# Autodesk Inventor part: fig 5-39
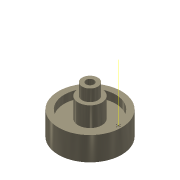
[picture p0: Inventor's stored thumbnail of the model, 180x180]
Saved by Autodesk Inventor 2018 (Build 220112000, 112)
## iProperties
Shininess: 65.0
Length Units: 11269
Angle Units: 11279
Time Units: 11290
Mass Units: 11283
Length Display Precision: 3
Angle Display Precision: 2
Created: 2001-11
Part Number: fig 5-39
Document SubType Name: Modeling
Designer: Renu Muthoo
Density: 1 g/cm^3
Material: Generic
Appearance: Metal-Titanium (Polished)
Density: 0.0
Volumn: 0.0
Area: 0.0
PropertySet Name: Model Information
Control State: 0
Master: False
Checked Out: False
Author: Renu Muthoo
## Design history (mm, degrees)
sketch "Sketch1"
  geometry: L1 (2.694, 30.112)-(5.194, 30.112); L2 (5.194, 30.112)-(5.194, 22.612); L3 (5.194, 22.612)-(7.694, 22.612); L4 (7.694, 22.612)-(7.694, 10.112); L5 (7.694, 10.112)-(16.444, 10.112); L6 (16.444, 10.112)-(16.444, 15.112); L7 (16.444, 15.112)-(20.194, 15.112); L8 (0.194, -4.034)-(0.194, 25.966); L9 (2.694, 30.112)-(2.694, 0.112); L10 (2.694, 0.112)-(20.194, 0.112); L11 (20.194, 0.112)-(20.194, 15.112)
  constraints: 22 end point, 7 parallel, 2 perpendicular, 1 horizontal
  dimensions: "d0" = 5 diameter of L9 L8; "d1" = 10 diameter of L2 L8; "d2" = 15 diameter of L4 L8; "d3" = 32.5 diameter of L6 L8; "d4" = 40 diameter of L11 L8; "d5" = 15 distance of L10.end L7.end; "d6" = 22.5 distance between parallel lines of L3 L10; "d7" = 30 distance between parallel lines of L1 L10; "d8" = 10 distance between parallel lines of L10 L5
revolve "Revolution1" sketch "Sketch1" stored, may be unused: angle "d9" = 90 deg
workaxis "Work Axis1"
sketch "Sketch2"
  geometry: 1 further point
node "Sketch3"
workaxis "Work Axis3"
body "Solid1"
